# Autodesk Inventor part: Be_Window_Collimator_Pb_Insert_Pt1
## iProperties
Shininess: 64.0
Length Units: 11269
Angle Units: 11279
Time Units: 11290
Mass Units: 11283
Length Display Precision: 3
Angle Display Precision: 2
Compacted: True
Part Number: Be_Window_Collimator_Pb_Insert_Pt1
Document SubType Name: Modeling
Created: 2004-07
Designer: John Blackburn
Manufacturer: Standard
Standards Organization: Custom
Material: Lead
Density: 0.0
Volumn: 0.0
Area: 0.0
PropertySet Name: Model Information
Control State: 0
Master: False
Checked Out: False
Author: John Blackburn
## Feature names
1. Revolution1
2. Hole1
3. Circular Pattern1
